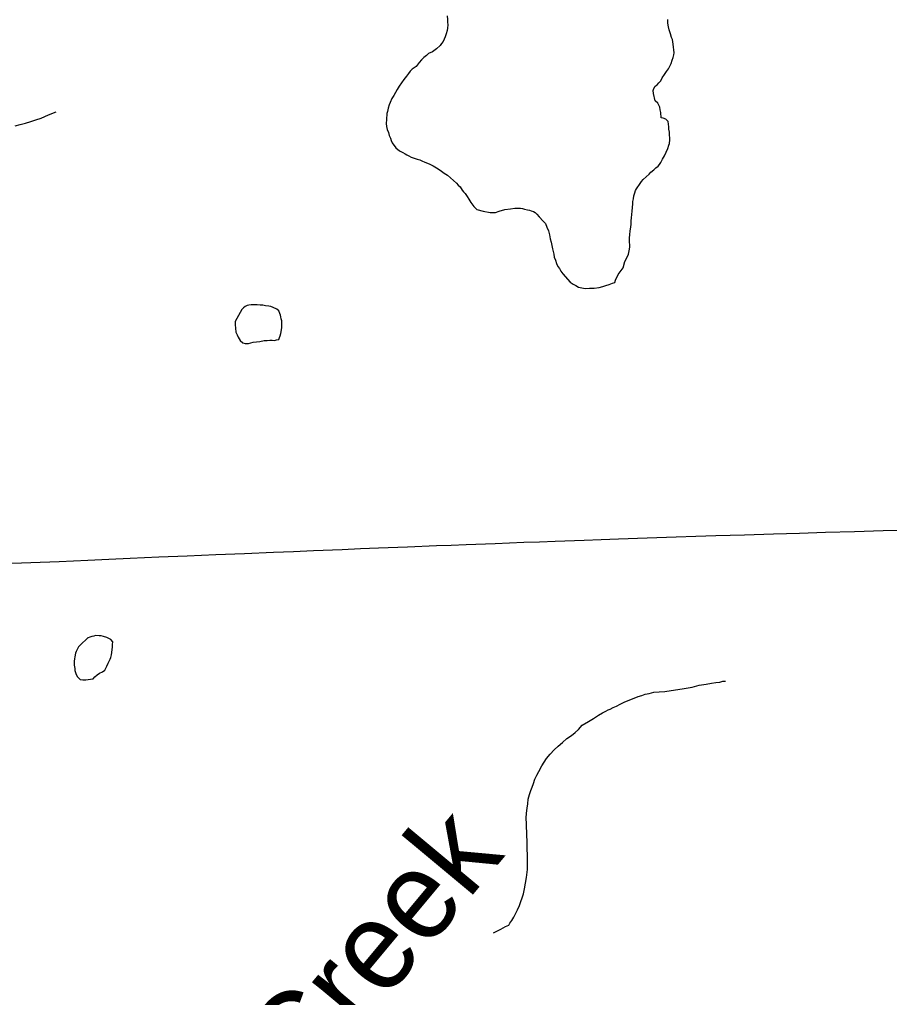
# Model space of a CAD drawing. Extents: x 103424 to 290657, y 38711 to 110967.
# Drawn here: x 135093 to 140062, y 49490 to 55076 of the extents above; entities that cross this region are included whole.
import ezdxf

# ---------------------------------------------------------------- set-up
doc = ezdxf.new("R2010")
doc.units = 0
for name, color, linetype in [('GM_X_Minor_Lake', 7, 'Continuous'), ('GM_X_Minor_River', 7, 'Continuous'), ('GM_X_Minor_River_Text', 7, 'Continuous'), ('GM_X_Township_Road', 7, 'Continuous')]:
    doc.layers.add(name, color=color, linetype=linetype)

msp = doc.modelspace()

# ---------------------------------------------------------------- linework, layer by layer
at = {"layer": 'GM_X_Minor_Lake'}
for points in [[(136590.9, 53316.6), (136590.6, 53330.7), (136590.3, 53344.8), (136590.1, 53354.9), (136587.9, 53367), (136585.6, 53377), (136583.4, 53387.1), (136579.1, 53397.1), (136572.8, 53411.1), (136562.4, 53420.9), (136542, 53430.6), (136527.7, 53436.3), (136515.6, 53438.1), (136497.3, 53439.7), (136483.1, 53443.4), (136466.9, 53445.1), (136450.7, 53446.8), (136432.5, 53446.4), (136416.4, 53446), (136402.3, 53443.7), (136392.2, 53441.5), (136382.2, 53437.2), (136372.3, 53428.9), (136362.4, 53418.6), (136323.4, 53351.1)], [(136323.4, 53351.1), (136323.8, 53331), (136326.3, 53312.8), (136328.7, 53290.7), (136335.2, 53274.7), (136341.5, 53260.7), (136352, 53242.7), (136368.5, 53229), (136380.7, 53225.2), (136400.9, 53225.6), (136427, 53232.3), (136465.3, 53237.1), (136489.5, 53241.7), (136507.6, 53242.1), (136521.7, 53244.4), (136535.9, 53244.7), (136548, 53243), (136560.1, 53245.3), (136574.2, 53247.6), (136578, 53259.8), (136581.8, 53269.9), (136585.6, 53282.1), (136589.2, 53302.4), (136590.9, 53316.6), (136590.6, 53330.7), (136590.3, 53344.8), (136590.1, 53354.9), (136587.9, 53367), (136585.6, 53377), (136583.4, 53387.1), (136579.1, 53397.1), (136572.8, 53411.1), (136562.4, 53420.9), (136542, 53430.6), (136527.7, 53436.3), (136515.6, 53438.1), (136497.3, 53439.7), (136483.1, 53443.4), (136466.9, 53445.1), (136450.7, 53446.8), (136432.5, 53446.4), (136416.4, 53446), (136402.3, 53443.7), (136392.2, 53441.5), (136382.2, 53437.2), (136372.3, 53428.9), (136362.4, 53418.6), (136323.4, 53351.1)], [(136323.4, 53351.1), (136323.8, 53331), (136326.3, 53312.8), (136328.7, 53290.7), (136335.2, 53274.7), (136341.5, 53260.7), (136352, 53242.7), (136368.5, 53229), (136380.7, 53225.2), (136400.9, 53225.6), (136427, 53232.3), (136465.3, 53237.1), (136489.5, 53241.7), (136507.6, 53242.1), (136521.7, 53244.4), (136535.9, 53244.7), (136548, 53243), (136560.1, 53245.3), (136574.2, 53247.6), (136578, 53259.8), (136581.8, 53269.9), (136585.6, 53282.1), (136589.2, 53302.4), (136590.9, 53316.6)], [(135482.1, 51543.2), (135439.3, 51502.8), (135429.4, 51492.5), (135421.6, 51478.2), (135415.8, 51466), (135412, 51455.8), (135408.4, 51435.6), (135406.6, 51423.4), (135404.9, 51411.3), (135405.1, 51399.1), (135405.4, 51387), (135407.8, 51368.9), (135408.1, 51356.8), (135416.6, 51334.8), (135423, 51320.8), (135439.5, 51305), (135453.7, 51303.3), (135471.9, 51303.7), (135498, 51308.3), (135512.1, 51310.6), (135522, 51320.9), (135535.9, 51333.3), (135549.9, 51341.7), (135565.9, 51350.1), (135579.8, 51358.5), (135591.4, 51383), (135599.2, 51399.3), (135605, 51411.6), (135610.8, 51421.8), (135614.6, 51432), (135618.4, 51446.2), (135623.5, 51490.7), (135623.1, 51506.8), (135624.9, 51521), (135614.5, 51534.9), (135592, 51546.5), (135571.6, 51552.2), (135559.4, 51555.9), (135547.3, 51555.7), (135527.1, 51557.2), (135517.1, 51553), (135505, 51550.7), (135494.9, 51548.5), (135484.9, 51544.2), (135482.1, 51543.2)], [(135482.1, 51543.2), (135439.3, 51502.8), (135429.4, 51492.5), (135421.6, 51478.2), (135415.8, 51466), (135412, 51455.8), (135408.4, 51435.6), (135406.6, 51423.4), (135404.9, 51411.3), (135405.1, 51399.1), (135405.4, 51387), (135407.8, 51368.9), (135408.1, 51356.8), (135416.6, 51334.8), (135423, 51320.8), (135439.5, 51305), (135453.7, 51303.3), (135471.9, 51303.7), (135498, 51308.3), (135512.1, 51310.6), (135522, 51320.9), (135535.9, 51333.3), (135549.9, 51341.7)], [(135549.9, 51341.7), (135565.9, 51350.1), (135579.8, 51358.5), (135591.4, 51383), (135599.2, 51399.3), (135605, 51411.6), (135610.8, 51421.8), (135614.6, 51432), (135618.4, 51446.2), (135623.5, 51490.7), (135623.1, 51506.8), (135624.9, 51521), (135614.5, 51534.9), (135592, 51546.5), (135571.6, 51552.2), (135559.4, 51555.9), (135547.3, 51555.7), (135527.1, 51557.2), (135517.1, 51553), (135505, 51550.7), (135494.9, 51548.5), (135484.9, 51544.2), (135482.1, 51543.2)]]:
    msp.add_lwpolyline(points, dxfattribs=at)
at = {"layer": 'GM_X_Minor_River'}
for points in [[(137535.2, 55097.6), (137537.7, 55075.5), (137538, 55061.3), (137538.3, 55045.2), (137536.7, 55027), (137535, 55012.8), (137529.3, 54994.5), (137523.6, 54976.2), (137512.1, 54949.7), (137502.2, 54939.4), (137494.3, 54927.1), (137474.5, 54908.5), (137450.6, 54891.9), (137428.6, 54881.3), (137416.7, 54870.9), (137402.8, 54858.5), (137388.9, 54846.1), (137375.2, 54829.7), (137357.4, 54807.1), (137335.5, 54792.5), (137323.7, 54780.1), (137313.8, 54767.8), (137302, 54751.4), (137288.3, 54732.9), (137274.5, 54714.4), (137260.8, 54695.9), (137249.1, 54675.5), (137239.3, 54659.1), (137229.6, 54642.8), (137219.9, 54624.4), (137210.2, 54602), (137204.5, 54587.7), (137198.8, 54569.4), (137195.2, 54551.2), (137191.4, 54539), (137188.1, 54504.6), (137186.5, 54482.3), (137188.9, 54464.2), (137193.3, 54448.2), (137199.8, 54430.1), (137204.1, 54414.1), (137210.6, 54398.1), (137214.9, 54384), (137221.2, 54372), (137242.1, 54342.2), (137262.6, 54326.5), (137281, 54316.8), (137295.3, 54309.1), (137305.6, 54303.2), (137315.8, 54297.4), (137330.1, 54289.6), (137346.4, 54283.9), (137364.7, 54278.3), (137378.9, 54274.5), (137391.2, 54268.7), (137407.5, 54261), (137432, 54251.5), (137454.5, 54239.8), (137474.9, 54228.2), (137495.4, 54214.5), (137518, 54198.8), (137536.4, 54187.1), (137554.9, 54171.4), (137571.4, 54155.6), (137587.9, 54141.8), (137598.3, 54129.9), (137608.6, 54120), (137621.1, 54102.1), (137629.4, 54092.2), (137637.7, 54082.3), (137650.2, 54064.4), (137658.6, 54050.4), (137671.1, 54030.5), (137687.8, 54008.7), (137704.3, 53990.9), (137740.9, 53981.6), (137781.5, 53974.4), (137811.8, 53973), (137831.9, 53981.5), (137864, 53990.3), (137896.2, 53995.1), (137922.5, 53997.6), (137934.6, 53997.9), (137944.7, 53998.1), (137954.8, 53998.4), (137964.9, 53996.5), (137977.1, 53992.8), (137993.4, 53989.1), (138005.6, 53987.3), (138015.7, 53983.5), (138027.9, 53979.7), (138038.2, 53973.9), (138046.5, 53964), (138061, 53948.2), (138083.7, 53924.4), (138096.1, 53910.6), (138104.6, 53890.6)], [(138789, 54779.6), (138798.8, 54794), (138808.5, 54812.4), (138814.3, 54824.6), (138820, 54842.9), (138825.7, 54859.2), (138829.4, 54873.4), (138831.2, 54885.5), (138830.8, 54903.7), (138828.5, 54917.8), (138826.1, 54935.9), (138823.8, 54948), (138821.5, 54962.1), (138817.2, 54974.1), (138810.7, 54994.1), (138804.2, 55016.2), (138799.7, 55034.3), (138795.3, 55054.3), (138794.8, 55076.6)], [(138104.6, 53890.6), (138113.2, 53868.5), (138119.7, 53846.5), (138124.3, 53822.4), (138128.7, 53804.3), (138133.2, 53784.2), (138137.6, 53766.1), (138140, 53750), (138144.3, 53736), (138146.7, 53717.9), (138153.1, 53701.8), (138159.6, 53681.8), (138168, 53665.8), (138176.4, 53653.9), (138184.8, 53637.9), (138195.2, 53624), (138238.7, 53576.5), (138255.1, 53564.8), (138269.4, 53557), (138285.8, 53547.2), (138304.1, 53543.6), (138324.3, 53540), (138348.6, 53540.5), (138374.8, 53541.1), (138403, 53545.8), (138425.2, 53550.3), (138441.2, 53556.7), (138461.3, 53563.2), (138479.3, 53569.6), (138493.4, 53574), (138497.2, 53586.2), (138512.6, 53618.8), (138528.3, 53641.4), (138540.1, 53657.8), (138549.4, 53694.3), (138563.1, 53718.8), (138570.8, 53735.2), (138574.4, 53755.4), (138578, 53775.7), (138577.7, 53787.8), (138577.4, 53806), (138576.9, 53828.1), (138578.5, 53846.4), (138580.1, 53868.6), (138583.7, 53888.9), (138585.3, 53907.1), (138586.9, 53925.3), (138588.6, 53943.5), (138590.2, 53961.7), (138591.8, 53981.9), (138593.4, 54002.1), (138595, 54022.4), (138596.7, 54036.5), (138600.4, 54050.7), (138602.1, 54068.9), (138607.8, 54085.2), (138611.5, 54099.4), (138617.4, 54109.7), (138637, 54138.4), (138644.8, 54150.6), (138654.6, 54163), (138672.5, 54177.5), (138688.4, 54192), (138698.2, 54204.3), (138716.1, 54216.8), (138728, 54229.2), (138739.9, 54237.5), (138747.8, 54247.8), (138755.6, 54260), (138765.3, 54278.4), (138777.1, 54296.9), (138786.7, 54317.3), (138796.4, 54339.7), (138802, 54358), (138805.9, 54368.1), (138807.5, 54388.4), (138807.2, 54400.5), (138804.9, 54414.6), (138804.5, 54432.7), (138802.1, 54448.8), (138801.8, 54462.9), (138799.5, 54479), (138797.1, 54493.1), (138784.7, 54507), (138768.4, 54512.7), (138758.3, 54514.5), (138755.6, 54544.7), (138751.2, 54560.8), (138750.9, 54574.9), (138738.3, 54598.9), (138723.9, 54610.7), (138712.9, 54652.8), (138712.5, 54671), (138716.3, 54681.2), (138724.1, 54695.5), (138734, 54703.7), (138743.9, 54714.1), (138755.8, 54726.4), (138763.5, 54742.7), (138777.3, 54761.2), (138789, 54779.6)], [(137799.7, 49858.9), (137840.8, 49879.5), (137868.8, 49894.2), (137886.8, 49902.7), (137892.6, 49914.9), (137904.4, 49929.3), (137916.2, 49947.8), (137925.8, 49968.1), (137937.5, 49990.6), (137949.1, 50015.1), (137971.9, 50082.2), (137977.3, 50110.6), (137982.7, 50143), (137988.1, 50175.4), (137993.2, 50219.9), (137994.6, 50250.2), (137993.9, 50282.5), (137993.3, 50308.8), (137992.8, 50333), (137992.2, 50361.2), (137991.6, 50387.5), (137991.1, 50409.7), (137990.6, 50435.9), (137988, 50460.1), (137987.6, 50482.3), (137986.9, 50514.5), (137988.3, 50542.8), (137991.7, 50571.2), (137995.2, 50595.5), (137998.7, 50621.8), (138006.2, 50648.2), (138013.8, 50672.6), (138021.5, 50690.9), (138029.1, 50711.3), (138036.7, 50735.7), (138048.3, 50760.1), (138058, 50780.5), (138075.5, 50813.2), (138089.2, 50833.7), (138102.9, 50854.2), (138122.6, 50878.9), (138146.3, 50903.6), (138170.1, 50924.3), (138193.9, 50947), (138219.7, 50969.8), (138245.6, 50986.5), (138265.4, 51003.1), (138285.3, 51019.7), (138307, 51044.4), (138342.9, 51065.3), (138370.8, 51084.1), (138398.7, 51102.9), (138422.7, 51115.5), (138440.7, 51126), (138454.7, 51132.4), (138466.7, 51136.6), (138482.7, 51145.1), (138502.7, 51153.6), (138522.7, 51164.1), (138546.7, 51176.8), (138626.8, 51208.8), (138646.9, 51215.3), (138667, 51221.8), (138689.1, 51226.3), (138715.3, 51232.9), (138745.5, 51235.6), (138777.8, 51238.3), (138814.1, 51243.1), (138852.4, 51248), (138888.6, 51254.8), (138934.9, 51261.9), (138975.1, 51272.9), (139015.4, 51279.8), (139045.6, 51284.5), (139069.8, 51289.1), (139091.9, 51291.6), (139110, 51296), (139118.1, 51296.2), (139124.2, 51296.3)]]:
    msp.add_lwpolyline(points, dxfattribs=at)
at = {"layer": 'GM_X_Township_Road'}
for points in [[(135066.7, 54468), (135096.9, 54475.6), (135126.9, 54483.9), (135156.6, 54492.9), (135186.1, 54502.7), (135215.2, 54513.3), (135236.9, 54521.8), (135258.6, 54530.6), (135302.1, 54548.9)], [(134994.5, 51968.5), (135156.2, 51974.4), (135317.9, 51980.3), (135482.7, 51988.2), (135603.1, 51994), (135723.5, 51999.8), (135888.4, 52006.5), (136050.7, 52013), (136213, 52019.6), (136377.9, 52026.3), (136542.8, 52033), (136657.1, 52037.7), (136771.3, 52042.3), (136936.3, 52049.1), (137039.9, 52053.4), (137143.6, 52057.7), (137308.5, 52064.1), (137473.5, 52070.6), (137558.8, 52073.9), (137644.1, 52077.2), (137809, 52083.5), (137973.9, 52089.8), (138062.9, 52093.2), (138151.9, 52096.5), (138316.9, 52102.6), (138415, 52106.2), (138513.2, 52109.7), (138678.1, 52115.2), (138843.1, 52120.8), (138956.2, 52124.5), (139069.3, 52128.3), (139234.3, 52133.2), (139399.3, 52138.2), (139548, 52142.6), (139696.6, 52147.1), (139861.6, 52151.8), (140026.6, 52156.5), (140191.6, 52161.1)]]:
    msp.add_lwpolyline(points, dxfattribs=at)

# ---------------------------------------------------------------- texts
at = {"layer": 'GM_X_Minor_River_Text'}
msp.add_text('Creek', height=503.37, rotation=50.2016, dxfattribs=at).set_placement((136719.6, 48921.2))

doc.saveas('drawing.dxf')
